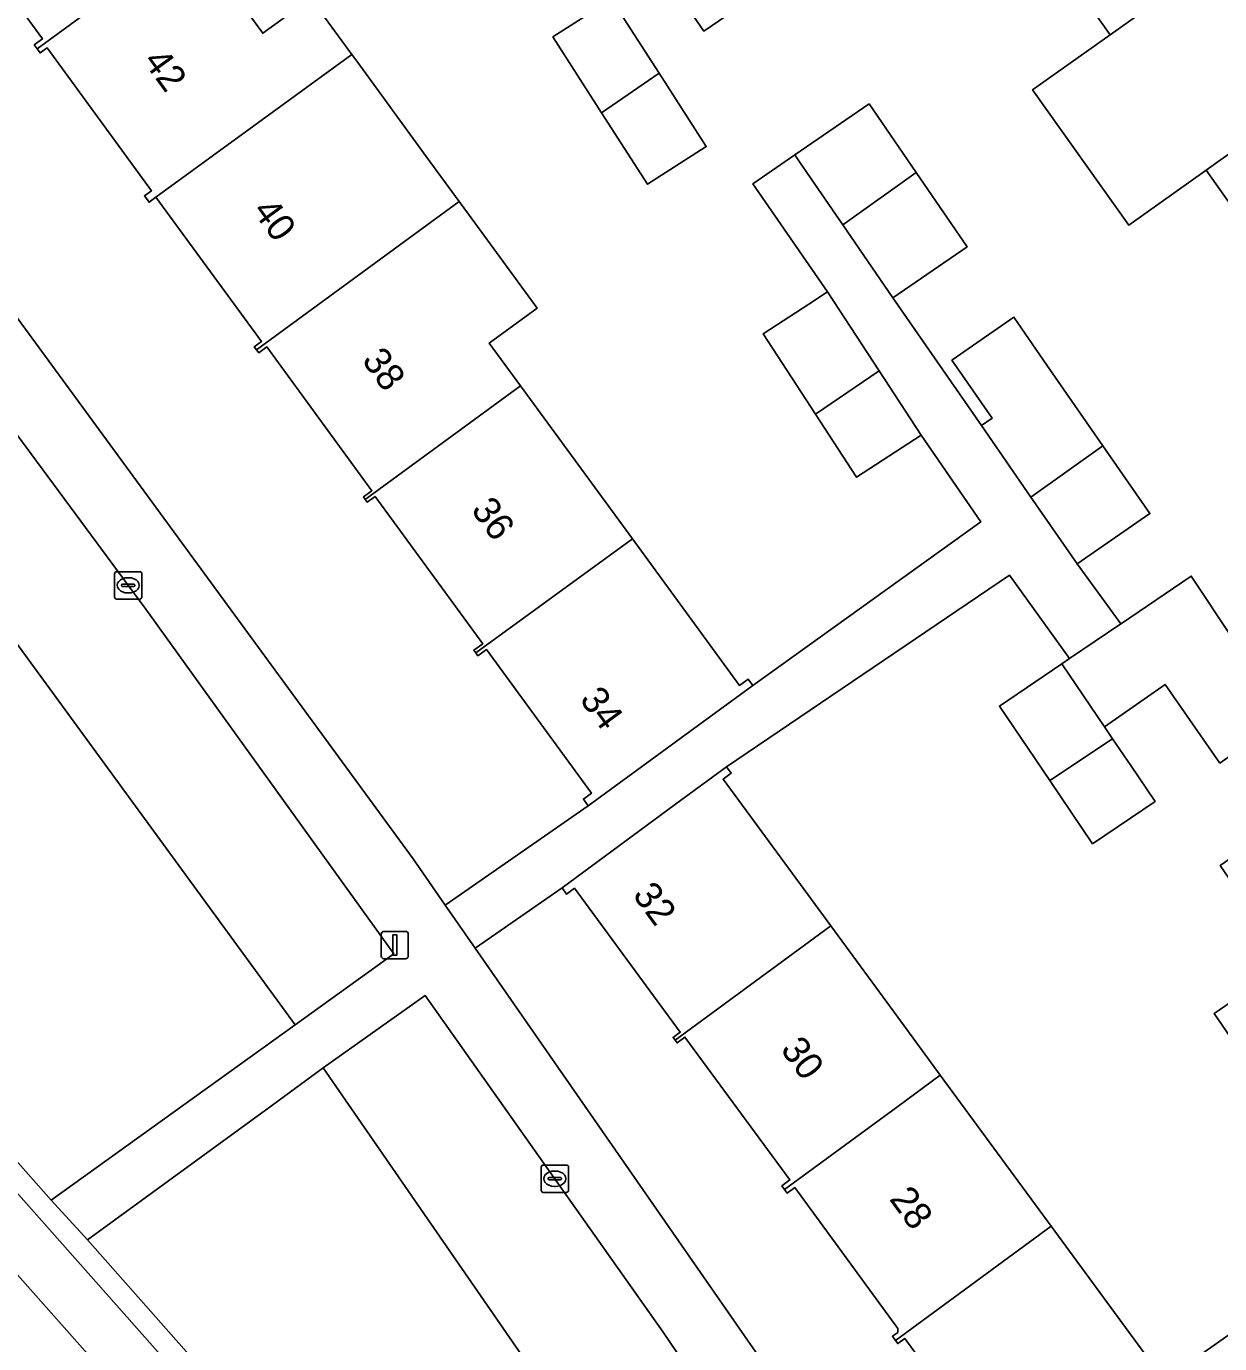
# Model space of a CAD drawing. Extents: x 157445 to 158888, y 383061 to 384688.
# Drawn here: x 157968.13 to 158011.77, y 383510.11 to 383558.3 of the extents above; entities that cross this region are included whole.
import ezdxf

# ---------------------------------------------------------------- set-up
doc = ezdxf.new("R2010")
doc.units = 0
for name, color, linetype in [('IMGEO_Erf', 7, 'Continuous'), ('IMGEO_Groenvoorziening', 7, 'Continuous'), ('IMGEO_Kolk', 7, 'Continuous'), ('IMGEO_Lichtmast', 7, 'Continuous'), ('IMGEO_Pand', 7, 'Continuous'), ('IMGEO_Pand_nummerreeks', 7, 'Continuous'), ('IMGEO_Parkeervlak_open', 7, 'Continuous'), ('IMGEO_Rijbaan_lokaal_gesloten', 7, 'Continuous'), ('IMGEO_Voetpad_open', 7, 'Continuous')]:
    doc.layers.add(name, color=color, linetype=linetype)

msp = doc.modelspace()

# ---------------------------------------------------------------- linework, layer by layer
at = {"layer": 'IMGEO_Erf'}
for points in [[(157965.119, 383551.269), (157982.271, 383527.85), (157983.448, 383526.155), (157988.678, 383529.787), (157988.501, 383530.029), (157988.794, 383530.244), (157984.952, 383535.501), (157984.646, 383535.277), (157984.572, 383535.378), (157984.498, 383535.48), (157984.821, 383535.716), (157980.882, 383541.106), (157980.592, 383540.894), (157980.522, 383540.99), (157980.454, 383541.083), (157980.765, 383541.311), (157976.92, 383546.573), (157976.624, 383546.357), (157976.542, 383546.469), (157976.462, 383546.579), (157976.722, 383546.768), (157972.866, 383552.045), (157972.617, 383551.863), (157972.447, 383552.096), (157972.706, 383552.286), (157968.884, 383557.516), (157968.628, 383557.329), (157968.52, 383557.477), (157968.413, 383557.623), (157968.717, 383557.846), (157964.929, 383563.029)], [(158014.764, 383548.114), (158011.275, 383553.039), (158008.447, 383551.029), (158004.933, 383555.973), (158007.768, 383557.989), (158004.292, 383562.895)], [(157974.169, 383561.61), (157976.773, 383558.046), (157978.527, 383559.328), (157980.031, 383557.27), (157980.246, 383556.975), (157982.754, 383553.543), (157983.959, 383551.895), (157984.302, 383551.426), (157986.81, 383547.993), (157985.056, 383546.712), (157986.201, 383545.145), (157990.292, 383539.548), (157994.208, 383534.189), (157994.526, 383534.422), (157994.698, 383534.186), (158003.037, 383540.171), (158000.852, 383543.345), (157998.493, 383541.808), (157996.99, 383544.113), (157995.076, 383547.05), (157996.749, 383548.141), (157997.435, 383548.588), (157994.703, 383552.543), (157996.23, 383553.598), (157998.95, 383555.464), (158000.677, 383552.948), (158002.536, 383550.238), (157999.816, 383548.371), (158003.058, 383543.695), (158003.448, 383543.965), (158001.98, 383546.087), (158004.247, 383547.656), (158005.457, 383545.909), (158007.504, 383542.953), (158009.22, 383540.473), (158006.563, 383538.633), (158008.161, 383536.443), (158008.183, 383536.458), (158010.734, 383538.188), (158012.229, 383535.933)], [(157995.629, 383559.987), (157992.909, 383558.12), (157991.479, 383560.205)], [(157989.711, 383559.006), (157991.269, 383556.582), (157992.993, 383553.901), (157990.85, 383552.523), (157989.167, 383555.142), (157987.386, 383557.912), (157989.528, 383559.29)], [(158011.784, 383531.348), (158010.782, 383532.788), (158009.779, 383534.227), (158007.558, 383532.68), (158007.856, 383532.24), (158008.522, 383531.257), (158009.41, 383529.946), (158007.128, 383528.4), (158005.559, 383530.717), (158003.719, 383533.433), (158006, 383534.979), (158006.281, 383535.17), (158004.089, 383538.223), (157993.741, 383531.213), (157993.909, 383530.985), (157993.608, 383530.764), (157997.548, 383525.395), (158000, 383522.053), (158001.555, 383519.934), (158005.612, 383514.405), (158009.571, 383509.009), (158009.87, 383509.228), (158010.049, 383508.984), (158019.772, 383515.834)], [(158013.353, 383519.593), (158011.575, 383522.191), (158014.242, 383524.015)]]:
    msp.add_lwpolyline(points, dxfattribs=at)
msp.add_lwpolyline([(157992.217, 383521.327), (157991.928, 383521.115), (157991.856, 383521.213), (157991.783, 383521.313), (157992.043, 383521.504), (157988.173, 383526.772), (157987.882, 383526.558), (157987.723, 383526.79), (157984.541, 383524.581), (158000.328, 383501.854), (158004.038, 383504.58), (158003.858, 383504.825), (158004.127, 383505.022), (158000.257, 383510.302), (158000, 383510.114), (157999.919, 383510.224), (157999.805, 383510.379), (158000, 383510.522), (158000, 383510.669), (157996.234, 383515.822), (157995.958, 383515.619), (157995.861, 383515.751), (157995.764, 383515.883), (157996.058, 383516.099)], close=True, dxfattribs=at)
at = {"layer": 'IMGEO_Groenvoorziening'}
for points in [[(157977.961, 383521.773), (157981.567, 383524.365), (157972.494, 383536.982), (157963.112, 383549.668), (157959.54, 383546.985)], [(157969.04, 383515.361), (157977.961, 383521.773), (157959.54, 383546.985), (157948.437, 383538.644)], [(157993.986, 383498.111), (157996.836, 383500), (157998.027, 383500.773), (157991.425, 383510.532), (157982.718, 383522.845), (157978.989, 383520.199), (157992.947, 383500)], [(157977.144, 383518.851), (157970.368, 383513.905), (157987.894, 383494.074), (157993.986, 383498.111), (157992.947, 383500), (157978.989, 383520.199)]]:
    msp.add_lwpolyline(points, close=True, dxfattribs=at)
at = {"layer": 'IMGEO_Kolk'}
for p, q in [((157971.352, 383537.425), (157971.352, 383538.277)), ((157971.427, 383538.351), (157972.279, 383538.351)), ((157972.353, 383538.277), (157972.353, 383537.425)), ((157971.611, 383537.845), (157971.611, 383537.857)), ((157972.049, 383537.808), (157971.651, 383537.808)), ((157971.654, 383537.894), (157972.052, 383537.894)), ((157971.84, 383538.131), (157971.865, 383538.131)), ((157972.095, 383537.857), (157972.095, 383537.845)), ((157972.279, 383537.351), (157971.427, 383537.351)), ((157971.863, 383537.571), (157971.838, 383537.571)), ((157986.956, 383515.719), (157986.956, 383516.571)), ((157987.031, 383516.645), (157987.883, 383516.645)), ((157987.957, 383516.571), (157987.957, 383515.719)), ((157987.215, 383516.139), (157987.215, 383516.151)), ((157987.653, 383516.102), (157987.255, 383516.102)), ((157987.258, 383516.188), (157987.656, 383516.188)), ((157987.444, 383516.425), (157987.469, 383516.425)), ((157987.699, 383516.151), (157987.699, 383516.139)), ((157987.883, 383515.645), (157987.031, 383515.645)), ((157987.467, 383515.865), (157987.442, 383515.865))]:
    msp.add_line(p, q, dxfattribs=at)
for points in [[(157971.352, 383537.425), (157971.352, 383538.277)], [(157971.427, 383538.351), (157972.279, 383538.351)], [(157972.353, 383538.277), (157972.353, 383537.425)], [(157972.279, 383537.351), (157971.427, 383537.351)], [(157986.956, 383515.719), (157986.956, 383516.571)], [(157987.031, 383516.645), (157987.883, 383516.645)], [(157987.957, 383516.571), (157987.957, 383515.719)], [(157987.883, 383515.645), (157987.031, 383515.645)]]:
    msp.add_lwpolyline(points, dxfattribs=at)
for centre, radius, start, end in [((157971.429, 383538.275), 0.0765, 91.552, 178.448), ((157971.429, 383538.275), 0.0765, 91.552, 178.448), ((157972.277, 383538.275), 0.0765, 1.552, 88.448), ((157972.277, 383538.275), 0.0765, 1.552, 88.448), ((157971.651, 383537.854), 0.0403, 85.8775, 175.7526), ((157971.648, 383537.844), 0.0366, 178.938, 274.7102), ((157972.052, 383537.851), 0.043, 264.8664, 352.4533), ((157972.056, 383537.856), 0.0386, 1.7309, 96.639), ((157971.429, 383537.427), 0.0765, 181.552, 268.448), ((157971.429, 383537.427), 0.0765, 181.552, 268.448), ((157972.277, 383537.427), 0.0765, 271.552, 358.448), ((157972.277, 383537.427), 0.0765, 271.552, 358.448), ((157987.033, 383516.569), 0.0765, 91.552, 178.448), ((157987.033, 383516.569), 0.0765, 91.552, 178.448), ((157987.881, 383516.569), 0.0765, 1.552, 88.448), ((157987.881, 383516.569), 0.0765, 1.552, 88.448), ((157987.255, 383516.148), 0.0403, 85.8775, 175.7526), ((157987.252, 383516.138), 0.0366, 178.938, 274.7102), ((157987.656, 383516.145), 0.043, 264.8664, 352.4533), ((157987.66, 383516.15), 0.0386, 1.7309, 96.639), ((157987.033, 383515.721), 0.0765, 181.552, 268.448), ((157987.033, 383515.721), 0.0765, 181.552, 268.448), ((157987.881, 383515.721), 0.0765, 271.552, 358.448), ((157987.881, 383515.721), 0.0765, 271.552, 358.448)]:
    msp.add_arc(centre, radius, start, end, dxfattribs=at)
for centre, major_axis, ratio, start_param, end_param in [((157971.839, 383537.851), (-0.387, 0.002), 0.722429, 4.712389, 7.853982), ((157971.864, 383537.851), (-0.39, 0.002), 0.717154, 1.570796, 4.712389), ((157987.443, 383516.145), (-0.387, 0.002), 0.722429, 4.712389, 7.853982), ((157987.468, 383516.145), (-0.39, 0.002), 0.717154, 1.570796, 4.712389)]:
    msp.add_ellipse(centre, major_axis=major_axis, ratio=ratio, start_param=start_param, end_param=end_param, dxfattribs=at)
at = {"layer": 'IMGEO_Lichtmast'}
for p, q in [((157981.207, 383525.191), (157981.997, 383525.191)), ((157981.997, 383525.191), (157981.207, 383525.191)), ((157981.107, 383524.291), (157981.107, 383525.091)), ((157981.107, 383525.091), (157981.107, 383524.291)), ((157982.097, 383525.091), (157982.097, 383524.291)), ((157982.097, 383524.291), (157982.097, 383525.091)), ((157981.997, 383524.191), (157981.207, 383524.191)), ((157981.207, 383524.191), (157981.997, 383524.191))]:
    msp.add_line(p, q, dxfattribs=at)
msp.add_lwpolyline([(157981.527, 383525.066), (157981.677, 383525.066), (157981.677, 383524.316), (157981.527, 383524.316), (157981.527, 383525.066)], dxfattribs=at)
for centre, start, end in [((157981.207, 383525.091), 90, 180), ((157981.207, 383525.091), 90, 180), ((157981.997, 383525.091), 0, 90), ((157981.997, 383525.091), 360, 90), ((157981.207, 383524.291), 180, 270), ((157981.207, 383524.291), 180, 270), ((157981.997, 383524.291), 270, 0), ((157981.997, 383524.291), 270, 0)]:
    msp.add_arc(centre, 0.1, start, end, dxfattribs=at)
at = {"layer": 'IMGEO_Pand'}
for points in [[(157974.169, 383561.61), (157975.744, 383562.761), (157974.047, 383565.084), (157972.472, 383563.933), (157970.205, 383567.034), (157964.565, 383562.908), (157964.634, 383562.813), (157964.929, 383563.029), (157968.717, 383557.846), (157968.413, 383557.623), (157968.52, 383557.477)], [(158007.768, 383557.989), (158013.25, 383561.886), (158009.774, 383566.791), (158004.292, 383562.895)], [(157993.77, 383562.697), (157991.08, 383560.786), (157991.479, 383560.205), (157992.909, 383558.12), (157995.629, 383559.987)], [(158013.25, 383561.886), (158007.768, 383557.989), (158004.933, 383555.973), (158008.447, 383551.029), (158011.275, 383553.039), (158016.758, 383556.936)], [(157980.031, 383557.27), (157978.527, 383559.328), (157976.773, 383558.046), (157974.169, 383561.61), (157968.52, 383557.477), (157968.628, 383557.329), (157968.884, 383557.516), (157972.706, 383552.286), (157972.447, 383552.096), (157972.617, 383551.863), (157972.866, 383552.045)], [(157989.711, 383559.006), (157989.528, 383559.29), (157987.386, 383557.912), (157989.167, 383555.142), (157991.269, 383556.582)], [(157983.959, 383551.895), (157982.754, 383553.543), (157980.246, 383556.975), (157980.031, 383557.27), (157972.866, 383552.045), (157976.722, 383546.768), (157976.462, 383546.579), (157976.542, 383546.469)], [(157989.167, 383555.142), (157990.85, 383552.523), (157992.993, 383553.901), (157991.269, 383556.582)], [(158011.275, 383553.039), (158014.764, 383548.114), (158020.247, 383552.012), (158016.758, 383556.936)], [(157998.95, 383555.464), (157996.23, 383553.598), (157996.427, 383553.311), (157997.987, 383551.036), (158000.677, 383552.948)], [(158000.677, 383552.948), (157997.987, 383551.036), (157999.816, 383548.371), (158002.536, 383550.238)], [(157985.056, 383546.712), (157986.81, 383547.993), (157984.302, 383551.426), (157983.959, 383551.895), (157976.542, 383546.469), (157976.624, 383546.357), (157976.92, 383546.573), (157980.765, 383541.311), (157980.454, 383541.083), (157980.522, 383540.99), (157986.201, 383545.145)], [(157996.99, 383544.113), (157999.314, 383545.704), (157997.435, 383548.588), (157996.749, 383548.141), (157995.076, 383547.05)], [(158005.457, 383545.909), (158004.247, 383547.656), (158001.98, 383546.087), (158003.448, 383543.965), (158003.058, 383543.695), (158004.869, 383541.079), (158007.504, 383542.953)], [(157996.99, 383544.113), (157998.493, 383541.808), (158000.852, 383543.345), (157999.314, 383545.704)], [(157980.522, 383540.99), (157980.592, 383540.894), (157980.882, 383541.106), (157984.821, 383535.716), (157984.498, 383535.48), (157984.572, 383535.378), (157990.292, 383539.548), (157986.201, 383545.145)], [(158007.504, 383542.953), (158004.869, 383541.079), (158006.563, 383538.633), (158009.22, 383540.473)], [(157990.292, 383539.548), (157984.572, 383535.378), (157984.646, 383535.277), (157984.952, 383535.501), (157988.794, 383530.244), (157988.501, 383530.029), (157988.678, 383529.787), (157992.716, 383532.737), (157994.698, 383534.186), (157994.526, 383534.422), (157994.208, 383534.189)], [(158012.229, 383535.933), (158010.734, 383538.188), (158008.183, 383536.458), (158008.161, 383536.443), (158006.281, 383535.17), (158006, 383534.979), (158007.558, 383532.68), (158009.779, 383534.227), (158010.782, 383532.788), (158011.784, 383531.348), (158014.218, 383533.078)], [(158006, 383534.979), (158003.719, 383533.433), (158005.559, 383530.717), (158007.856, 383532.24), (158007.558, 383532.68)], [(158007.856, 383532.24), (158005.559, 383530.717), (158007.128, 383528.4), (158009.41, 383529.946), (158008.522, 383531.257)], [(157997.548, 383525.395), (157993.608, 383530.764), (157993.909, 383530.985), (157993.741, 383531.213), (157991.876, 383529.842), (157987.723, 383526.79), (157987.882, 383526.558), (157988.173, 383526.772), (157992.043, 383521.504), (157991.783, 383521.313), (157991.856, 383521.213)], [(157997.548, 383525.395), (157991.856, 383521.213), (157991.928, 383521.115), (157992.217, 383521.327), (157996.058, 383516.099), (157995.764, 383515.883), (157995.861, 383515.751), (158000, 383518.792), (158001.555, 383519.934), (158000, 383522.053)], [(158013.353, 383519.593), (158016.039, 383521.39), (158014.242, 383524.015), (158011.575, 383522.191)], [(158005.612, 383514.405), (158001.555, 383519.934), (158000, 383518.792), (157995.861, 383515.751), (157995.958, 383515.619), (157996.234, 383515.822), (158000, 383510.669), (158000, 383510.522), (157999.805, 383510.379), (157999.919, 383510.224)], [(158005.612, 383514.405), (157999.919, 383510.224), (158000, 383510.114), (158000.257, 383510.302), (158004.127, 383505.022), (158003.858, 383504.825), (158004.038, 383504.58), (158008.072, 383507.536), (158010.049, 383508.984), (158009.87, 383509.228), (158009.571, 383509.009)]]:
    msp.add_lwpolyline(points, close=True, dxfattribs=at)
at = {"layer": 'IMGEO_Parkeervlak_open'}
for points in [[(158000.095, 383477.951), (157997.202, 383482.054), (157992.065, 383488.205), (157983.378, 383498.016), (157930.01, 383558.3)], [(157928.672, 383556.808), (157992.101, 383485.193)]]:
    msp.add_lwpolyline(points, dxfattribs=at)
at = {"layer": 'IMGEO_Rijbaan_lokaal_gesloten'}
msp.add_lwpolyline([(157992.101, 383485.193), (157928.672, 383556.808)], dxfattribs=at)
at = {"layer": 'IMGEO_Voetpad_open'}
for points in [[(158012.356, 383483.697), (158001.189, 383500.638), (158000.328, 383501.854), (157984.541, 383524.581), (157983.448, 383526.155), (157982.271, 383527.85), (157965.119, 383551.269), (157962.879, 383554.327), (157933.255, 383591.676)], [(157970.368, 383513.905), (157969.04, 383515.361), (157948.437, 383538.644), (157947.148, 383540.101), (157930.621, 383558.778)], [(157930.01, 383558.3), (157983.378, 383498.016), (157992.065, 383488.205), (157997.202, 383482.054), (158000.095, 383477.951)], [(157963.112, 383549.668), (157972.494, 383536.982), (157981.567, 383524.365), (157977.961, 383521.773), (157969.04, 383515.361), (157970.368, 383513.905), (157977.144, 383518.851), (157978.989, 383520.199), (157982.718, 383522.845), (157991.425, 383510.532), (157998.027, 383500.773)], [(157996.15, 383484.634), (157989.142, 383492.696), (157987.894, 383494.074), (157970.368, 383513.905)]]:
    msp.add_lwpolyline(points, dxfattribs=at)
for points in [[(157999.816, 383548.371), (157997.987, 383551.036), (157996.427, 383553.311), (157996.23, 383553.598), (157994.703, 383552.543), (157997.435, 383548.588), (157999.314, 383545.704), (158000.852, 383543.345), (158003.037, 383540.171), (157994.698, 383534.186), (157992.716, 383532.737), (157988.678, 383529.787), (157983.448, 383526.155), (157984.541, 383524.581), (157987.723, 383526.79), (157991.876, 383529.842), (157993.741, 383531.213), (158004.089, 383538.223), (158006.281, 383535.17), (158008.161, 383536.443), (158006.563, 383538.633), (158004.869, 383541.079), (158003.058, 383543.695)], [(158022.011, 383514.66), (158021.699, 383515.093), (158022.224, 383515.472), (158020.039, 383518.82), (158018.49, 383521.194), (158016.469, 383524.288), (158013.542, 383528.823), (158011.787, 383527.601), (158014.242, 383524.015), (158016.039, 383521.39), (158017.816, 383518.792), (158019.772, 383515.834), (158010.049, 383508.984), (158008.072, 383507.536), (158004.038, 383504.58), (158000.328, 383501.854), (158001.189, 383500.638), (158005.096, 383503.397), (158009.303, 383506.368), (158012.33, 383508.373), (158015.265, 383510.171)]]:
    msp.add_lwpolyline(points, close=True, dxfattribs=at)

# ---------------------------------------------------------------- texts
at = {"layer": 'IMGEO_Pand_nummerreeks'}
for s, rotation, p in [('42', 306.1649, (157972.37, 383557.024)), ('40', 306.1649, (157976.372, 383551.548)), ('38', 306.1649, (157980.372, 383546.077)), ('36', 306.1665, (157984.368, 383540.607)), ('34', 306.3393, (157988.337, 383533.671)), ('32', 306.2756, (157990.275, 383526.523)), ('30', 306.3046, (157995.683, 383520.869)), ('28', 306.1607, (157999.666, 383515.399))]:
    msp.add_text(s, height=1, rotation=rotation, dxfattribs=at).set_placement(p)

doc.saveas('drawing.dxf')
